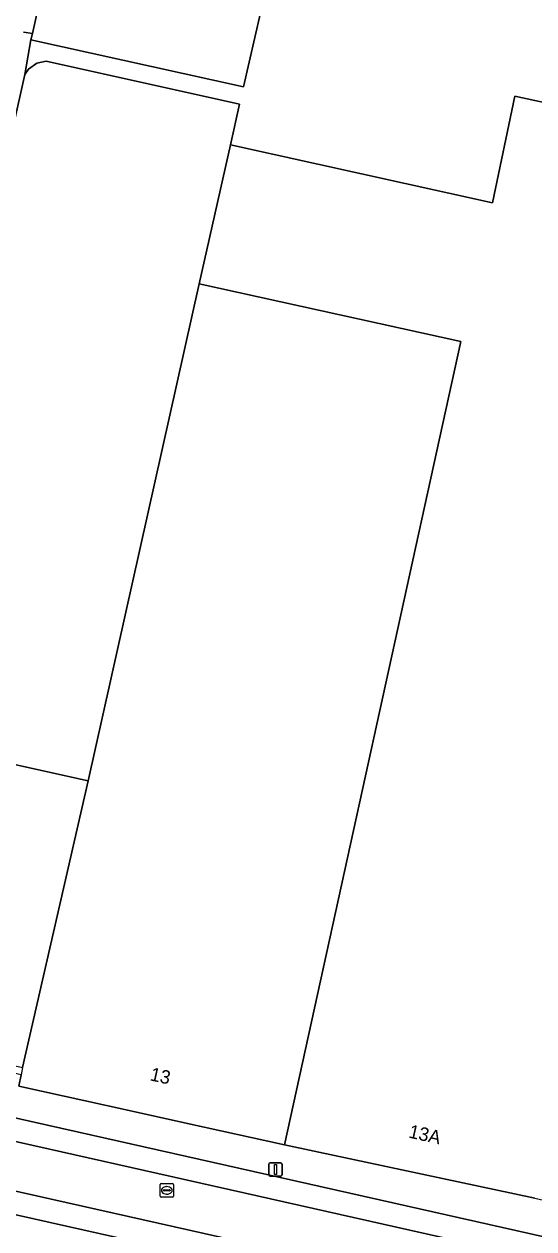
# Model space of a CAD drawing. Extents: x 162172 to 163187, y 382874 to 383685.
# Drawn here: x 162587.5 to 162625.4, y 383012.1 to 383101.7 of the extents above; entities that cross this region are included whole.
import ezdxf

# ---------------------------------------------------------------- set-up
doc = ezdxf.new("R2010")
doc.units = 0
for name, color, linetype in [('IMGEO_Erf', 7, 'Continuous'), ('IMGEO_Lichtmast', 7, 'Continuous'), ('IMGEO_Pand', 7, 'Continuous'), ('IMGEO_Pand_nummerreeks', 7, 'Continuous'), ('IMGEO_Parkeervlak_open', 7, 'Continuous'), ('IMGEO_Rijbaan_lokaal_gesloten', 7, 'Continuous'), ('IMGEO_Rioolput', 7, 'Continuous'), ('IMGEO_Voetpad_open', 7, 'Continuous')]:
    doc.layers.add(name, color=color, linetype=linetype)

msp = doc.modelspace()

# ---------------------------------------------------------------- linework, layer by layer
at = {"layer": 'IMGEO_Erf'}
msp.add_lwpolyline([(162605.924, 383106.249), (162603.809, 383097.034), (162588.005, 383100.532), (162587.542, 383097.969), (162587.817, 383098.35), (162588.453, 383098.802), (162589.13, 383098.96), (162603.52, 383095.749), (162602.842, 383092.735), (162622.337, 383088.423), (162624.01, 383096.356), (162637.988, 383093.329), (162638.985, 383093.108), (162639.962, 383097.521), (162642.483, 383096.964), (162642.83, 383098.534), (162645.457, 383097.953), (162645.843, 383099.698), (162678.511, 383092.388), (162679.725, 383097.876), (162670.276, 383099.967), (162653.057, 383103.778)], dxfattribs=at)
at = {"layer": 'IMGEO_Lichtmast'}
for p, q in [((162605.693, 383016.094), (162605.693, 383016.894)), ((162605.693, 383016.894), (162605.693, 383016.094)), ((162605.793, 383016.994), (162606.583, 383016.994)), ((162606.583, 383016.994), (162605.793, 383016.994)), ((162606.683, 383016.894), (162606.683, 383016.094)), ((162606.683, 383016.094), (162606.683, 383016.894)), ((162606.583, 383015.994), (162605.793, 383015.994)), ((162605.793, 383015.994), (162606.583, 383015.994))]:
    msp.add_line(p, q, dxfattribs=at)
msp.add_lwpolyline([(162606.113, 383016.869), (162606.263, 383016.869), (162606.263, 383016.119), (162606.113, 383016.119), (162606.113, 383016.869)], dxfattribs=at)
for centre, start, end in [((162605.793, 383016.894), 90, 180), ((162605.793, 383016.894), 90, 180), ((162606.583, 383016.894), 0, 90), ((162606.583, 383016.894), 360, 90), ((162605.793, 383016.094), 180, 270), ((162605.793, 383016.094), 180, 270), ((162606.583, 383016.094), 270, 0), ((162606.583, 383016.094), 270, 0)]:
    msp.add_arc(centre, 0.1, start, end, dxfattribs=at)
at = {"layer": 'IMGEO_Pand'}
for points in [[(162607.662, 383113.818), (162591.717, 383117.299), (162588.111, 383101.011), (162588.005, 383100.532), (162603.809, 383097.034), (162605.924, 383106.249)], [(162600.513, 383082.384), (162602.842, 383092.735), (162603.52, 383095.749), (162589.13, 383098.96), (162588.453, 383098.802), (162587.817, 383098.35), (162587.542, 383097.969), (162577.465, 383052.811), (162577.413, 383052.58), (162576.647, 383049.119), (162576.596, 383048.889), (162592.267, 383045.42)], [(162644.132, 383091.969), (162638.985, 383093.108), (162637.988, 383093.329), (162624.01, 383096.356), (162622.337, 383088.423), (162602.842, 383092.735), (162600.513, 383082.384), (162619.98, 383078.109), (162606.861, 383018.331), (162609.084, 383017.857), (162623.985, 383014.678), (162625.479, 383014.359), (162626.455, 383014.14), (162626.494, 383014.317), (162626.54, 383014.523), (162626.931, 383016.265), (162630.828, 383033.645), (162632.449, 383040.877), (162632.905, 383040.777)], [(162619.98, 383078.109), (162600.513, 383082.384), (162592.267, 383045.42), (162587.376, 383024.078), (162587.271, 383023.55), (162587.103, 383022.704), (162595.302, 383020.889), (162599.651, 383019.927), (162606.861, 383018.331)], [(162592.267, 383045.42), (162576.596, 383048.889), (162575.223, 383042.685), (162578.933, 383041.864), (162578.529, 383040.039), (162573.778, 383041.091), (162571.334, 383030.049), (162572.761, 383027.312), (162583.241, 383024.993), (162587.376, 383024.078)]]:
    msp.add_lwpolyline(points, close=True, dxfattribs=at)
at = {"layer": 'IMGEO_Parkeervlak_open'}
msp.add_lwpolyline([(162633.717, 383002.605), (162579.914, 383014.696)], dxfattribs=at)
at = {"layer": 'IMGEO_Rijbaan_lokaal_gesloten'}
for points in [[(162829.302, 382965.805), (162824.157, 382966.963), (162787.291, 382975.248), (162773.34, 382978.384), (162571.899, 383023.687), (162571.522, 383022.029), (162786.88, 382973.603), (162917.14, 382944.312), (162943.106, 382938.499), (163087.202, 382906.239), (163087.933, 382911.374)], [(163083.281, 382900.241), (163086.245, 382899.688), (163087.202, 382906.239), (162943.106, 382938.499), (162917.14, 382944.312), (162786.88, 382973.603), (162571.522, 383022.029), (162570.463, 383017.371), (162571.857, 383017.418)], [(162582.55, 383015.84), (162786.012, 382970.134), (162942.339, 382935.016), (163063.468, 382907.805)], [(162786.012, 382970.134), (162582.55, 383015.84)], [(162578.735, 383014.966), (162579.914, 383014.696), (162633.717, 383002.605), (162634.011, 383002.544), (162686.729, 382990.692), (162687.058, 382990.622), (162702.086, 382987.23), (162742.081, 382978.256), (162742.474, 382978.167), (162785.592, 382968.454), (162799.197, 382965.389), (162799.607, 382965.303), (162822.549, 382960.121), (162914.534, 382939.493), (162915.372, 382939.293), (162941.966, 382933.318), (162958.833, 382929.528), (162973.588, 382926.269), (162974.816, 382925.987), (163061.72, 382906.535), (163062.776, 382906.254), (163065.631, 382905.242)]]:
    msp.add_lwpolyline(points, dxfattribs=at)
at = {"layer": 'IMGEO_Rioolput'}
for p, q in [((162597.611, 383014.516), (162597.611, 383015.368)), ((162597.686, 383015.442), (162598.538, 383015.442)), ((162597.913, 383014.985), (162598.311, 383014.985)), ((162598.099, 383015.222), (162598.124, 383015.222)), ((162598.612, 383015.368), (162598.612, 383014.516)), ((162598.538, 383014.442), (162597.686, 383014.442)), ((162597.87, 383014.936), (162597.87, 383014.948)), ((162598.308, 383014.899), (162597.91, 383014.899)), ((162598.122, 383014.662), (162598.097, 383014.662)), ((162598.354, 383014.948), (162598.354, 383014.936))]:
    msp.add_line(p, q, dxfattribs=at)
for points in [[(162597.611, 383014.516), (162597.611, 383015.368)], [(162597.686, 383015.442), (162598.538, 383015.442)], [(162598.612, 383015.368), (162598.612, 383014.516)], [(162598.538, 383014.442), (162597.686, 383014.442)]]:
    msp.add_lwpolyline(points, dxfattribs=at)
for centre, radius, start, end in [((162597.688, 383015.366), 0.0765, 91.55205, 178.44795), ((162597.688, 383015.366), 0.0765, 91.55205, 178.44795), ((162597.91, 383014.945), 0.0403, 85.87752, 175.75265), ((162598.315, 383014.947), 0.0386, 1.73085, 96.63898), ((162598.536, 383015.366), 0.0765, 1.55205, 88.44795), ((162598.536, 383015.366), 0.0765, 1.55205, 88.44795), ((162597.688, 383014.518), 0.0765, 181.55205, 268.44795), ((162597.688, 383014.518), 0.0765, 181.55205, 268.44795), ((162597.907, 383014.935), 0.0366, 178.93798, 274.71019), ((162598.311, 383014.942), 0.043, 264.86636, 352.45326), ((162598.536, 383014.518), 0.0765, 271.55205, 358.44795), ((162598.536, 383014.518), 0.0765, 271.55205, 358.44795)]:
    msp.add_arc(centre, radius, start, end, dxfattribs=at)
for centre, major_axis, ratio, start_param, end_param in [((162598.098, 383014.942), (-0.387, 0.002), 0.722429, 4.712389, 7.853982), ((162598.123, 383014.942), (-0.39, 0.002), 0.717154, 1.570796, 4.712389)]:
    msp.add_ellipse(centre, major_axis=major_axis, ratio=ratio, start_param=start_param, end_param=end_param, dxfattribs=at)
at = {"layer": 'IMGEO_Voetpad_open'}
for points in [[(162587.454, 383101.104), (162588.111, 383101.011), (162591.717, 383117.299), (162586.656, 383118.417), (162585.234, 383111.98), (162584.187, 383107.254), (162579.85, 383108.231), (162578.357, 383101.491), (162581.137, 383100.866), (162580.025, 383095.859), (162577.214, 383096.517), (162575.844, 383090.279), (162574.753, 383085.311), (162572.387, 383074.686), (162571.587, 383071.156), (162568.264, 383056.423), (162565.915, 383046.006), (162565.695, 383045.02), (162565.066, 383042.173)], [(162576.878, 383052.958), (162577.465, 383052.811), (162587.542, 383097.969), (162588.005, 383100.532), (162588.111, 383101.011), (162587.454, 383101.104)], [(162625.479, 383014.359), (162623.985, 383014.678), (162609.084, 383017.857), (162606.861, 383018.331), (162599.651, 383019.927), (162595.302, 383020.889), (162587.103, 383022.704), (162587.271, 383023.55), (162572.984, 383026.76), (162572.034, 383026.977), (162571.622, 383027.04), (162570.901, 383023.915), (162571.899, 383023.687), (162773.34, 382978.384)]]:
    msp.add_lwpolyline(points, dxfattribs=at)

# ---------------------------------------------------------------- texts
at = {"layer": 'IMGEO_Pand_nummerreeks'}
for s, rotation, p in [('13', 347.51525, (162596.809, 383023.136)), ('13A', 347.52098, (162616.049, 383018.877))]:
    msp.add_text(s, height=1, rotation=rotation, dxfattribs=at).set_placement(p)

doc.saveas('drawing.dxf')
